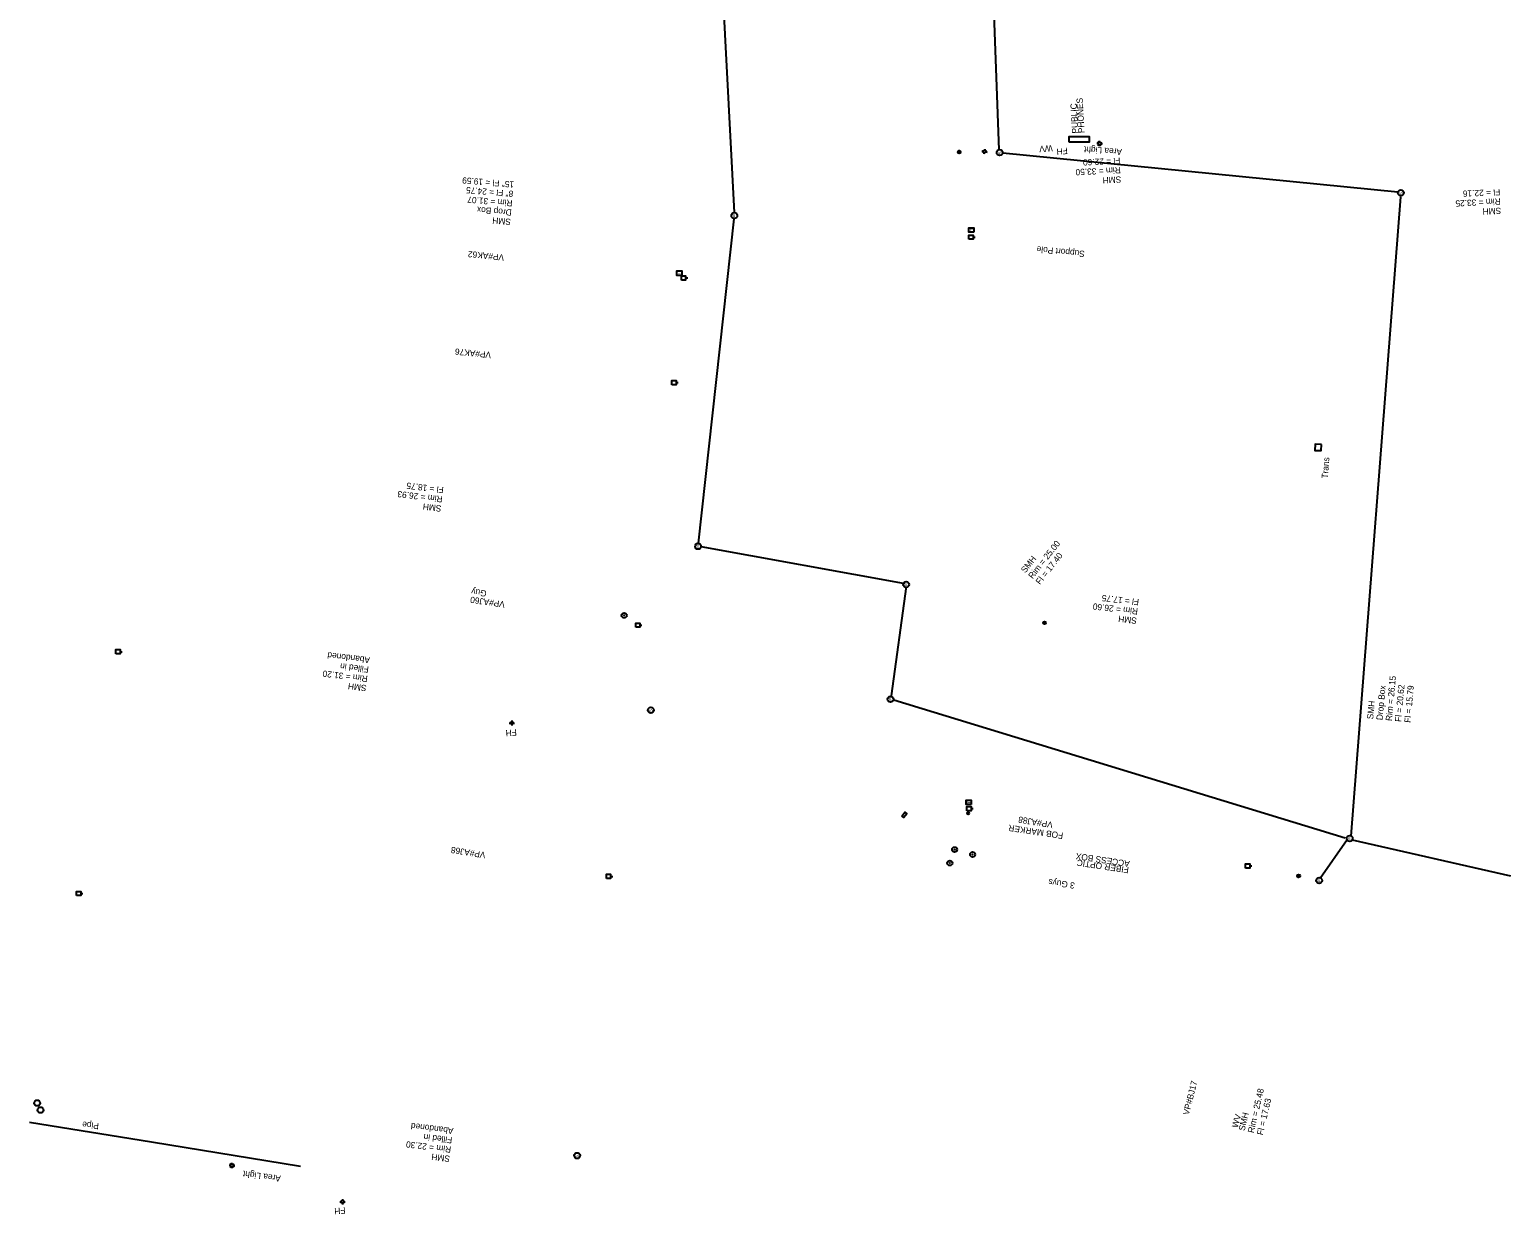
# Model space of a CAD drawing. Extents: x 3872070 to 3879223, y 293944 to 310567.
# Drawn here: x 3876217 to 3876927, y 299492 to 300060 of the extents above; entities that cross this region are included whole.
import ezdxf

# ---------------------------------------------------------------- set-up
doc = ezdxf.new("R2010")
doc.units = 0
for name, color, linetype in [('Level 10', 7, 'Continuous'), ('Level 11', 7, 'Continuous'), ('Level 3', 7, 'Continuous'), ('Level 33', 7, 'Continuous'), ('Level 34', 7, 'Continuous'), ('Level 35', 7, 'Continuous'), ('Level 37', 7, 'Continuous'), ('Level 4', 7, 'Continuous'), ('Level 40', 7, 'Continuous'), ('Level 41', 7, 'Continuous'), ('Level 5', 7, 'Continuous'), ('Level 6', 7, 'Continuous'), ('Level 7', 7, 'Continuous')]:
    doc.layers.add(name, color=color, linetype=linetype)

msp = doc.modelspace()

# ---------------------------------------------------------------- linework, layer by layer
at = {"layer": 'Level 10'}
msp.add_lwpolyline([(3876635.37, 299682.71), (3876636.78, 299684.59), (3876637.74, 299683.87), (3876636.34, 299681.99)], close=True, dxfattribs=at)
msp.add_circle((3876667.22, 299684.01), 0.5, dxfattribs=at)
at = {"layer": 'Level 11'}
msp.add_lwpolyline([(3876216.85, 299535.81), (3876275.38, 299526.43), (3876346.84, 299514.67)], dxfattribs=at)
for centre in [(3876220.48, 299545.01), (3876222.03, 299541.66)]:
    msp.add_circle(centre, 1.41, dxfattribs=at)
at = {"layer": 'Level 3'}
for p, q in [((3876682.13, 300002.53), (3876669.64, 300345.55)), ((3876555.06, 299972.34), (3876538.83, 300281.01)), ((3876873.39, 299982.14), (3876683.93, 300000.88)), ((3876851.03, 299673.13), (3876874.83, 299979.92)), ((3876537.81, 299813.72), (3876554.98, 299969.37)), ((3876636.21, 299794.33), (3876539.13, 299811.89)), ((3876637.47, 299792.91), (3876630.33, 299740.39)), ((3876631.53, 299738.47), (3876848.18, 299672.35)), ((3876849.14, 299671.27), (3876836.17, 299652.79)), ((3876851.55, 299671.39), (3876927.45, 299654.11))]:
    msp.add_line(p, q, dxfattribs=at)
for centre in [(3876682.35, 300001.14), (3876874.84, 299981.78), (3876555.04, 299970.9), (3876537.62, 299812.16), (3876637.53, 299793.85), (3876629.96, 299738.77), (3876514.93, 299733.59), (3876850.34, 299671.98), (3876835.68, 299651.82), (3876479.63, 299519.77)]:
    msp.add_circle(centre, 1.41, dxfattribs=at)
at = {"layer": 'Level 4'}
for p, q in [((3876729.61, 300005.45), (3876729.03, 300005.45)), ((3876729.82, 300005.96), (3876729.42, 300006.36)), ((3876729.42, 300004.53), (3876729.82, 300004.93)), ((3876730.33, 300006.17), (3876730.33, 300006.75)), ((3876730.33, 300004.72), (3876730.33, 300004.15)), ((3876730.85, 300005.96), (3876731.25, 300006.36)), ((3876731.25, 300004.53), (3876730.85, 300004.93)), ((3876731.06, 300005.45), (3876731.63, 300005.45)), ((3876669.58, 299960.55), (3876670.58, 299960.55)), ((3876531.67, 299940.98), (3876532.67, 299940.98)), ((3876527.06, 299890.74), (3876528.06, 299890.74)), ((3876509.72, 299774.35), (3876510.72, 299774.35)), ((3876260.27, 299761.6), (3876261.27, 299761.6)), ((3876668.63, 299686.28), (3876669.63, 299686.28)), ((3876495.65, 299653.8), (3876496.65, 299653.8)), ((3876802.38, 299658.8), (3876803.38, 299658.8)), ((3876241.38, 299645.6), (3876242.38, 299645.6)), ((3876313.23, 299515), (3876312.66, 299515)), ((3876313.45, 299515.51), (3876313.04, 299515.92)), ((3876313.04, 299514.08), (3876313.45, 299514.48)), ((3876313.96, 299515.72), (3876313.96, 299516.3)), ((3876313.96, 299514.27), (3876313.96, 299513.7)), ((3876314.47, 299515.51), (3876314.88, 299515.92)), ((3876314.88, 299514.08), (3876314.47, 299514.48)), ((3876314.69, 299515), (3876315.26, 299515))]:
    msp.add_line(p, q, dxfattribs=at)
for points in [[(3876667.58, 299959.55), (3876667.58, 299961.55), (3876669.58, 299961.55), (3876669.58, 299959.55)], [(3876529.67, 299939.98), (3876529.67, 299941.98), (3876531.67, 299941.98), (3876531.67, 299939.98)], [(3876525.06, 299889.74), (3876525.06, 299891.74), (3876527.06, 299891.74), (3876527.06, 299889.74)], [(3876507.72, 299773.35), (3876507.72, 299775.35), (3876509.72, 299775.35), (3876509.72, 299773.35)], [(3876258.27, 299760.6), (3876258.27, 299762.6), (3876260.27, 299762.6), (3876260.27, 299760.6)], [(3876666.63, 299685.28), (3876666.63, 299687.28), (3876668.63, 299687.28), (3876668.63, 299685.28)], [(3876493.65, 299652.8), (3876493.65, 299654.8), (3876495.65, 299654.8), (3876495.65, 299652.8)], [(3876800.38, 299657.8), (3876800.38, 299659.8), (3876802.38, 299659.8), (3876802.38, 299657.8)], [(3876239.38, 299644.6), (3876239.38, 299646.6), (3876241.38, 299646.6), (3876241.38, 299644.6)]]:
    msp.add_lwpolyline(points, close=True, dxfattribs=at)
msp.add_lwpolyline([(3876836.73, 299861.02), (3876833.73, 299861.14), (3876833.62, 299858.21), (3876836.62, 299858.1), (3876836.73, 299861.02)], dxfattribs=at)
for centre, radius in [((3876730.33, 300005.45), 0.725), ((3876502.16, 299779), 1.22), ((3876502.16, 299779), 0.0992), ((3876502.16, 299779), 0.0483), ((3876660.75, 299666.65), 1.22), ((3876658.44, 299660.17), 1.22), ((3876658.44, 299660.17), 0.0992), ((3876658.44, 299660.17), 0.0483), ((3876660.75, 299666.65), 0.0992), ((3876660.75, 299666.65), 0.0483), ((3876669.38, 299664.28), 1.22), ((3876669.38, 299664.28), 0.0992), ((3876669.38, 299664.28), 0.0483), ((3876313.96, 299515), 0.725)]:
    msp.add_circle(centre, radius, dxfattribs=at)
at = {"layer": 'Level 5'}
for p, q in [((3876662.05, 300001.55), (3876662.41, 300001.48)), ((3876662.41, 300001.48), (3876663.39, 300001.29)), ((3876663.39, 300001.29), (3876663.75, 300001.23)), ((3876673.83, 300001.85), (3876674.44, 300001.74)), ((3876675.29, 300002.85), (3876675.18, 300002.23)), ((3876675.67, 300001.51), (3876676.29, 300001.39)), ((3876674.94, 300001.01), (3876674.83, 300000.39)), ((3876447.01, 299727.38), (3876447.63, 299727.38)), ((3876448.26, 299728.63), (3876448.26, 299728)), ((3876448.26, 299726.76), (3876448.26, 299726.13)), ((3876448.87, 299727.38), (3876449.51, 299727.38)), ((3876825.76, 299654.49), (3876825.71, 299654.85)), ((3876825.93, 299653.5), (3876825.76, 299654.49)), ((3876825.98, 299653.14), (3876825.93, 299653.5)), ((3876365.73, 299497.63), (3876366.35, 299497.63)), ((3876366.98, 299498.88), (3876366.98, 299498.24)), ((3876366.98, 299497.01), (3876366.98, 299496.38)), ((3876367.59, 299497.63), (3876368.23, 299497.63))]:
    msp.add_line(p, q, dxfattribs=at)
for centre, radius in [((3876662.9, 300001.38), 0.7), ((3876675.06, 300001.62), 0.625), ((3876448.26, 299727.38), 0.625), ((3876825.84, 299653.99), 0.7), ((3876366.98, 299497.63), 0.625)]:
    msp.add_circle(centre, radius, dxfattribs=at)
for centre, start, end in [((3876662.9, 300001.38), 349.223, 169.223), ((3876825.84, 299653.99), 99.2281, 279.2281)]:
    msp.add_arc(centre, 0.5, start, end, dxfattribs=at)
at = {"layer": 'Level 6'}
for radius in [0.7, 0.188]:
    msp.add_circle((3876703.83, 299775.44), radius, dxfattribs=at)
at = {"layer": 'Level 7'}
for points in [[(3876715.67, 300006.14), (3876715.67, 300008.78), (3876725.27, 300008.78), (3876725.27, 300006.14)], [(3876669.96, 299962.89), (3876667.56, 299962.89), (3876667.56, 299965.08), (3876669.96, 299965.08)], [(3876529.76, 299942.2), (3876527.36, 299942.2), (3876527.36, 299944.39), (3876529.76, 299944.39)], [(3876668.71, 299688.2), (3876666.31, 299688.2), (3876666.31, 299690.39), (3876668.71, 299690.39)]]:
    msp.add_lwpolyline(points, close=True, dxfattribs=at)

# ---------------------------------------------------------------- texts
at = {"layer": 'Level 3'}
for rotation, p in [(279.01833, (3876681.57, 300001.5)), (279.01833, (3876874.06, 299982.13)), (183.45194, (3876555.47, 299971.64)), (182.44389, (3876538.06, 299812.89)), (189.2281, (3876637.88, 299794.63)), (189.2281, (3876630.31, 299739.54)), (270, (3876514.22, 299734.06)), (189.2281, (3876850.69, 299672.76)), (189.2281, (3876836.04, 299652.6)), (270, (3876478.91, 299520.25))]:
    msp.add_text('S', height=1.41, rotation=rotation, dxfattribs=at).set_placement(p)
at = {"layer": 'Level 33'}
for s, rotation, p in [('Rim = 33.50', 182.67614, (3876740.41, 299994.21)), ('Fl = 22.60', 182.67614, (3876740.2, 299998.71)), ('15" Fl = 19.59', 175.17456, (3876449.44, 299987.24)), ('SMH', 182.67614, (3876740.62, 299989.72)), ('8" Fl = 24.75', 175.17456, (3876449.06, 299982.76)), ('Rim = 31.07', 175.17456, (3876448.68, 299978.27)), ('Fl = 22.16', 182.67614, (3876922.52, 299983.7)), ('Drop Box', 175.17456, (3876448.3, 299973.79)), ('Rim = 33.25', 182.67614, (3876922.73, 299979.21)), ('SMH', 182.67614, (3876922.94, 299974.71)), ('SMH', 175.17456, (3876447.92, 299969.31)), ('Rim = 26.93', 173.05657, (3876415.16, 299836.17)), ('Fl = 18.75', 173.05657, (3876415.7, 299840.64)), ('SMH', 173.05657, (3876414.61, 299831.71)), ('Rim = 25.00', 51.74601, (3876698.17, 299796.35)), ('SMH', 51.74601, (3876694.64, 299799.13)), ('Fl = 17.40', 51.74601, (3876701.7, 299793.56)), ('Fl = 17.75', 173.33386, (3876749.38, 299786.82)), ('Rim = 26.60', 173.33386, (3876748.86, 299782.35)), ('SMH', 173.33386, (3876748.34, 299777.88)), ('Abandoned', 173.05657, (3876380.31, 299758.93)), ('Rim = 31.20', 173.05657, (3876379.22, 299750)), ('Filled in ', 173.05657, (3876379.76, 299754.47)), ('SMH', 173.05657, (3876378.67, 299745.53)), ('Drop Box', 84.7058, (3876866.07, 299728.65)), ('Rim = 26.15', 84.7058, (3876870.55, 299728.23)), ('Fl = 20.62', 84.7058, (3876875.03, 299727.82)), ('Fl = 15.79', 84.7058, (3876879.51, 299727.4)), ('SMH', 84.7058, (3876861.59, 299729.06)), ('Rim = 25.48', 76.84652, (3876804.27, 299530.42)), ('Fl = 17.63', 76.84652, (3876808.65, 299529.4)), ('SMH', 76.84652, (3876799.89, 299531.45)), ('Abandoned', 173.05657, (3876420.36, 299533.04)), ('Rim = 22.30', 173.05657, (3876419.27, 299524.1)), ('Filled in ', 173.05657, (3876419.81, 299528.57)), ('SMH', 173.05657, (3876418.73, 299519.64))]:
    msp.add_text(s, height=3, rotation=rotation, dxfattribs=at).set_placement(p)
at = {"layer": 'Level 34'}
for s, rotation, p in [('Area Light', 176.14622, (3876741.14, 300002.9)), ('VP#AK62', 174.14466, (3876444.67, 299952.2)), ('Support Pole', 174.14466, (3876723.32, 299953.9)), ('VP#AK76', 174.14466, (3876438.43, 299905.4)), ('Trans', 85.32416, (3876839.8, 299844.6)), ('VP#AJ60', 171.79212, (3876445.09, 299785.69)), ('Guy', 171.04667, (3876436.32, 299790.86)), ('VP#AJ88', 170.73007, (3876708.07, 299679.87)), ('VP#AJ68', 170.73007, (3876435.82, 299665.35)), ('3 Guys', 171.7403, (3876718.56, 299650.77)), ('VP#BJ17', 75.66753, (3876773.14, 299539.08)), ('Area Light', 172.6725, (3876337.54, 299510.17))]:
    msp.add_text(s, height=3, rotation=rotation, dxfattribs=at).set_placement(p)
at = {"layer": 'Level 35'}
for s, rotation, p in [('WV', 184.45303, (3876707.67, 300004.77)), ('FH', 184.45303, (3876714.88, 300003.46)), ('FH', 184.45303, (3876450.51, 299724.42)), ('WV', 74.33652, (3876796.58, 299532.93)), ('FH', 184.45303, (3876368.31, 299494.96))]:
    msp.add_text(s, height=3, rotation=rotation, dxfattribs=at).set_placement(p)
at = {"layer": 'Level 37'}
for s, p in [('PUBLIC ', (3876720.1, 300010.37)), ('PHONES', (3876723.12, 300010.54))]:
    msp.add_text(s, height=3, rotation=93.20767, dxfattribs=at).set_placement(p)
at = {"layer": 'Level 40'}
for s, p in [('FOB MARKER', (3876713.02, 299674.68)), ('ACCESS BOX', (3876744.96, 299661.2)), ('FIBER OPTIC ', (3876744.52, 299658.21))]:
    msp.add_text(s, height=3, rotation=171.52351, dxfattribs=at).set_placement(p)
at = {"layer": 'Level 41'}
msp.add_text('Pipe', height=3, rotation=174.2876, dxfattribs=at).set_placement((3876250.21, 299535.39))
at = {"layer": 'Level 7'}
for p in [(3876669.53, 299963.41), (3876529.33, 299942.72), (3876668.28, 299688.72)]:
    msp.add_text('T', height=1.41, rotation=90, dxfattribs=at).set_placement(p)

doc.saveas('drawing.dxf')
